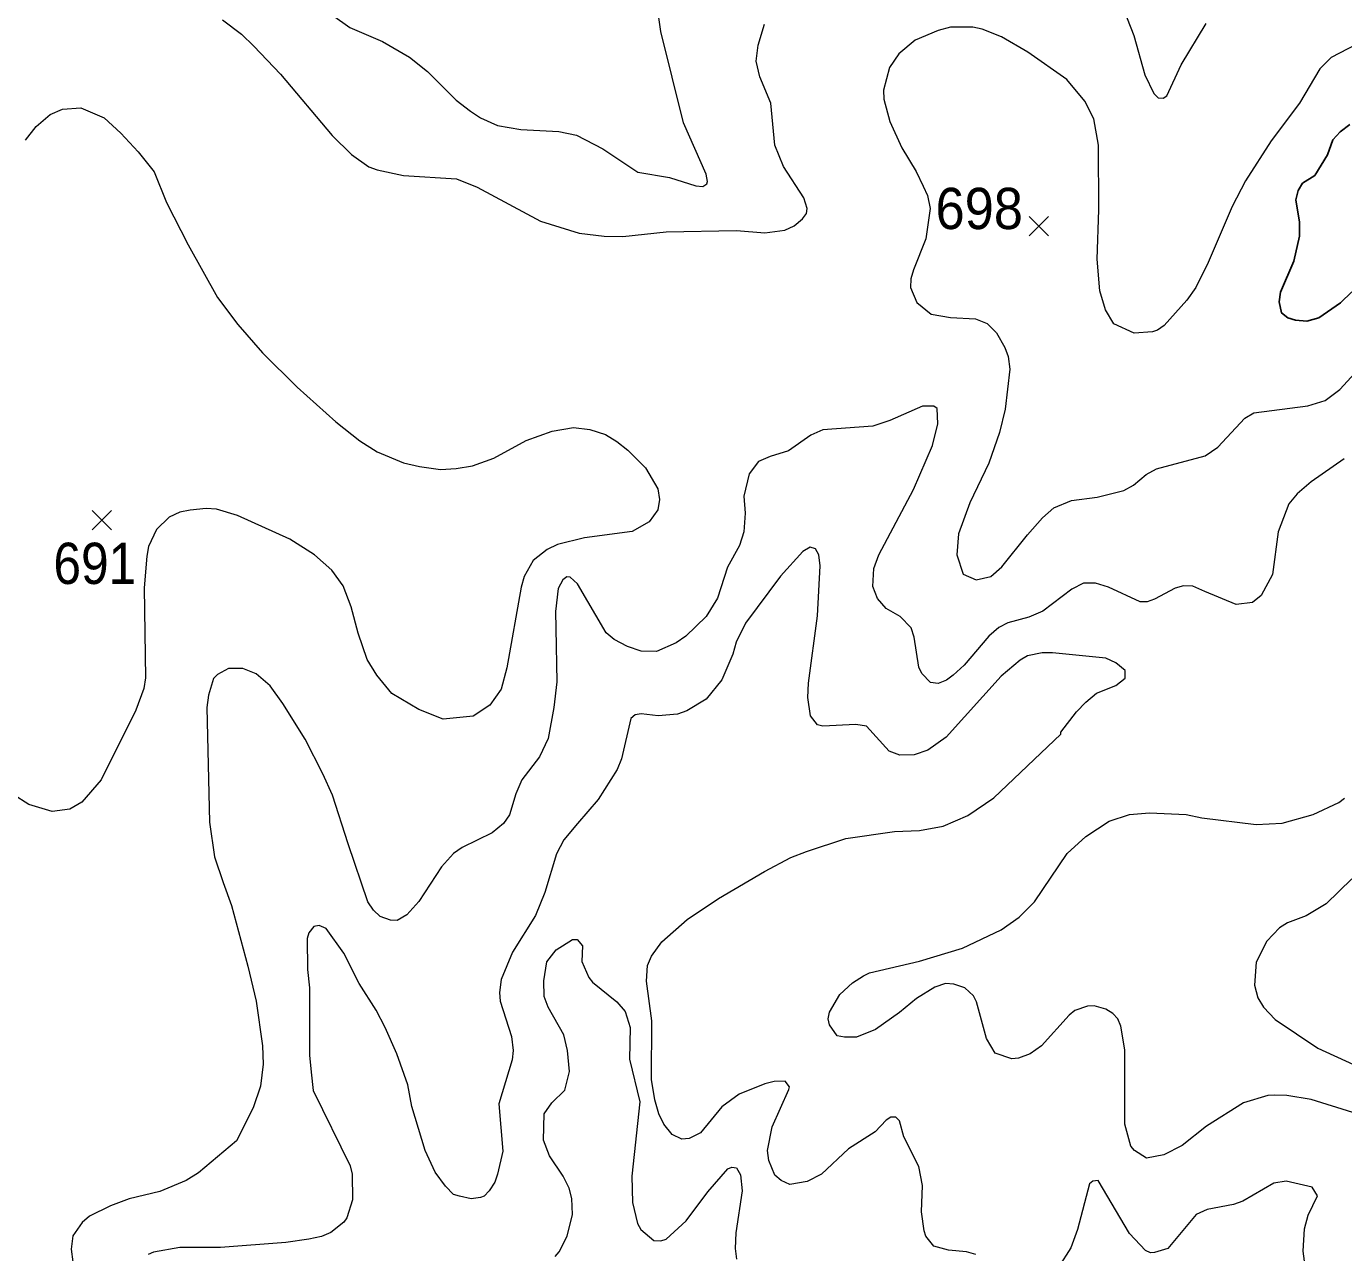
# Model space of a CAD drawing. Extents: x 294.2 to 320.3, y 7482.7 to 7510.7.
# Drawn here: x 301.736 to 304.291, y 7497.059 to 7499.438 of the extents above; entities that cross this region are included whole.
import ezdxf
from ezdxf.enums import TextEntityAlignment as Align

# ---------------------------------------------------------------- set-up
doc = ezdxf.new("R2010")
doc.units = 0
doc.header["$LTSCALE"] = 0.032
for name, color, linetype, lineweight in [('1', 7, 'Continuous', 25), ('2', 7, 'Continuous', 13), ('21', 7, 'Continuous', 25)]:
    doc.layers.add(name, color=color, linetype=linetype, lineweight=lineweight)
doc.layers.add('61', color=7, linetype='Continuous')

msp = doc.modelspace()

# ---------------------------------------------------------------- linework, layer by layer
at = {"layer": '1'}
msp.add_lwpolyline([(304.3071, 7498.9229), (304.2851, 7498.9017), (304.2434, 7498.8726), (304.2198, 7498.8663), (304.1978, 7498.8679), (304.1829, 7498.8726), (304.1711, 7498.8821), (304.1664, 7498.9033), (304.1687, 7498.9222), (304.195, 7498.9827), (304.206, 7499.0307), (304.206, 7499.0582), (304.1986, 7499.1014), (304.2033, 7499.1195), (304.2119, 7499.1337), (304.2355, 7499.1486), (304.2599, 7499.1887), (304.2705, 7499.2178), (304.2847, 7499.2335), (304.3035, 7499.2477)], dxfattribs=at)
at = {"layer": '2'}
for points in [[(302.3298, 7499.4594), (302.3636, 7499.4357), (302.4268, 7499.4083), (302.4792, 7499.3782), (302.5143, 7499.3502), (302.5366, 7499.3278), (302.5698, 7499.2946), (302.5979, 7499.2735), (302.6171, 7499.2608), (302.6503, 7499.2454), (302.695, 7499.2378), (302.7691, 7499.234), (302.8035, 7499.227), (302.8546, 7499.2002), (302.9223, 7499.1548), (302.9836, 7499.1446), (303.0347, 7499.1286), (303.0481, 7499.1274), (303.0563, 7499.1324), (303.0576, 7499.137), (303.0545, 7499.151), (303.011, 7499.2506), (302.9669, 7499.4281), (302.9631, 7499.4549)], [(303.8646, 7499.4715), (303.8845, 7499.4204), (303.9055, 7499.3438), (303.9234, 7499.308), (303.9317, 7499.2991), (303.9413, 7499.2985), (303.9483, 7499.3029), (303.9764, 7499.363), (304.0249, 7499.4434)], [(302.1165, 7499.4504), (302.1536, 7499.423), (302.1772, 7499.3993), (302.2289, 7499.3451), (302.3291, 7499.2263), (302.3668, 7499.1893), (302.4006, 7499.1657), (302.4166, 7499.1593), (302.4677, 7499.1484), (302.5705, 7499.142), (302.6107, 7499.1261), (302.7333, 7499.0603), (302.8087, 7499.0367), (302.8572, 7499.0309), (302.8929, 7499.0303), (302.9772, 7499.0393), (303.1138, 7499.0418), (303.1687, 7499.0373), (303.2071, 7499.0424), (303.2256, 7499.0507), (303.2415, 7499.0648), (303.2492, 7499.075), (303.2504, 7499.0846), (303.244, 7499.105), (303.2051, 7499.1663), (303.1879, 7499.2072), (303.1802, 7499.2889), (303.1592, 7499.34), (303.1521, 7499.3706), (303.1559, 7499.4013), (303.1681, 7499.4421)], [(303.5289, 7499.4364), (303.5046, 7499.43), (303.4599, 7499.4109), (303.4286, 7499.3846), (303.4107, 7499.3579), (303.3986, 7499.3144), (303.3992, 7499.2966), (303.4113, 7499.2532), (303.4343, 7499.2021), (303.4624, 7499.1567), (303.4759, 7499.128), (303.4841, 7499.1101), (303.4892, 7499.0846), (303.481, 7499.0259), (303.4567, 7498.9658), (303.4516, 7498.948), (303.4509, 7498.9314), (303.4637, 7498.902), (303.4911, 7498.8796), (303.5289, 7498.8733), (303.5774, 7498.8707), (303.5997, 7498.8617), (303.6182, 7498.8432), (303.6342, 7498.8152), (303.6406, 7498.7973), (303.6437, 7498.773), (303.6348, 7498.6951), (303.624, 7498.6504), (303.6029, 7498.5904), (303.5665, 7498.5138), (303.5441, 7498.4538), (303.541, 7498.4129), (303.5531, 7498.3752), (303.5787, 7498.3643), (303.6067, 7498.3708), (303.6285, 7498.3893), (303.6782, 7498.4518), (303.707, 7498.4844), (303.7293, 7498.5042), (303.7638, 7498.5183), (303.8136, 7498.5246), (303.8647, 7498.5374), (303.8838, 7498.5482), (303.9081, 7498.5687), (303.9285, 7498.5796), (304.023, 7498.6051), (304.0473, 7498.6217), (304.0996, 7498.6779), (304.1175, 7498.6881), (304.2222, 7498.7021), (304.2554, 7498.7124), (304.2841, 7498.7334), (304.3282, 7498.7813)], [(303.7893, 7499.2927), (303.7542, 7499.3349), (303.6789, 7499.3879), (303.6278, 7499.4178), (303.5901, 7499.4326), (303.5723, 7499.4364), (303.5289, 7499.4364)], [(304.3467, 7499.4191), (304.2675, 7499.3776), (304.2452, 7499.3553), (304.2056, 7499.2889), (304.1507, 7499.2161), (304.1009, 7499.1382), (304.0754, 7499.0884), (304.0288, 7498.9799), (304.0045, 7498.9314), (303.9872, 7498.9071), (303.9432, 7498.8579), (303.9304, 7498.8483), (303.9209, 7498.8452), (303.8851, 7498.8426), (303.8455, 7498.8611), (303.8296, 7498.8879), (303.8187, 7498.925), (303.8136, 7498.9863), (303.8168, 7499.082), (303.8161, 7499.2072), (303.8066, 7499.2583), (303.7893, 7499.2927)], [(301.7347, 7499.2174), (301.7551, 7499.2436), (301.782, 7499.2672), (301.8062, 7499.2774), (301.842, 7499.2799), (301.8867, 7499.2602), (301.9192, 7499.2308), (301.9531, 7499.1944), (301.9837, 7499.1555), (302.008, 7499.0961), (302.0501, 7499.0144), (302.1069, 7498.9122), (302.1465, 7498.8598), (302.1944, 7498.8049), (302.2615, 7498.7379), (302.3362, 7498.6708), (302.3827, 7498.6338), (302.4166, 7498.6128), (302.4677, 7498.591), (302.4984, 7498.584), (302.5392, 7498.5783), (302.5699, 7498.5802), (302.6018, 7498.5853), (302.6426, 7498.6), (302.7058, 7498.6345), (302.7563, 7498.6529), (302.7972, 7498.66), (302.8291, 7498.6562), (302.8597, 7498.646), (302.8814, 7498.6325), (302.9031, 7498.6159), (302.937, 7498.5815), (302.9612, 7498.5406), (302.9644, 7498.5202), (302.9612, 7498.4998), (302.944, 7498.4767), (302.9114, 7498.4582), (302.8189, 7498.4455), (302.7665, 7498.4327), (302.7461, 7498.4231), (302.7192, 7498.4021), (302.702, 7498.3708), (302.6962, 7498.3503), (302.6681, 7498.1933), (302.6573, 7498.1524), (302.6349, 7498.1211), (302.6031, 7498.1), (302.5449, 7498.0943), (302.4971, 7498.1128), (302.4453, 7498.1441), (302.416, 7498.1792), (302.3974, 7498.2099), (302.3795, 7498.261), (302.3662, 7498.312), (302.3509, 7498.3529), (302.3285, 7498.3829), (302.2947, 7498.4129), (302.2474, 7498.4429), (302.1459, 7498.4889), (302.1051, 7498.5017), (302.0846, 7498.5029), (302.054, 7498.4997), (302.0335, 7498.4953), (302.0131, 7498.4857), (301.9882, 7498.4621), (301.9729, 7498.4289), (301.9696, 7498.4104), (301.9645, 7498.3491)], [(303.6029, 7498.2552), (303.555, 7498.199), (303.534, 7498.1792), (303.5212, 7498.1697), (303.5046, 7498.1633), (303.4899, 7498.1651), (303.4733, 7498.1824), (303.4675, 7498.1946), (303.4586, 7498.2533), (303.4522, 7498.2712), (303.4312, 7498.2935), (303.4037, 7498.3088), (303.3871, 7498.328), (303.3781, 7498.3516), (303.3801, 7498.3861), (303.3896, 7498.4129), (303.4567, 7498.5393), (303.4937, 7498.6249), (303.5045, 7498.667), (303.5027, 7498.6964), (303.4963, 7498.7015), (303.4745, 7498.7015), (303.4114, 7498.6734), (303.3782, 7498.6626), (303.2811, 7498.6555), (303.2581, 7498.6447), (303.2147, 7498.6146), (303.179, 7498.6038), (303.156, 7498.5936), (303.1381, 7498.57), (303.1278, 7498.5266), (303.1304, 7498.4934), (303.1278, 7498.4576), (303.1196, 7498.4308), (303.0959, 7498.3887), (303.0768, 7498.3286), (303.0551, 7498.2935), (303.0155, 7498.2552), (302.9964, 7498.2418), (302.9587, 7498.2252), (302.9287, 7498.2258), (302.9019, 7498.2348), (302.8763, 7498.2488), (302.861, 7498.2616), (302.8055, 7498.3567), (302.7908, 7498.3695), (302.7844, 7498.3701), (302.7767, 7498.3643), (302.7677, 7498.3478), (302.7626, 7498.3031), (302.7633, 7498.2699), (302.7652, 7498.1665), (302.7595, 7498.1167), (302.748, 7498.0566), (302.7314, 7498.0209), (302.6975, 7497.9762), (302.6854, 7497.9494), (302.6732, 7497.9085), (302.6618, 7497.8919), (302.6394, 7497.8734), (302.5814, 7497.8453), (302.5648, 7497.8332), (302.5411, 7497.8076), (302.4977, 7497.7406), (302.4741, 7497.7144), (302.4556, 7497.7036), (302.4422, 7497.7042), (302.4223, 7497.7112), (302.4096, 7497.7233), (302.3987, 7497.74), (302.3604, 7497.8523), (302.3297, 7497.9468), (302.3113, 7497.9877), (302.2768, 7498.0554), (302.2334, 7498.1243), (302.2091, 7498.1588), (302.1816, 7498.1817), (302.1561, 7498.1926), (302.128, 7498.1926), (302.1069, 7498.1805), (302.0993, 7498.1728), (302.0891, 7498.1409), (302.0859, 7498.1167), (302.0916, 7497.8945), (302.1012, 7497.8268), (302.1178, 7497.777), (302.1338, 7497.7323), (302.1657, 7497.6148), (302.1816, 7497.5471), (302.1944, 7497.4603), (302.1951, 7497.4246), (302.19, 7497.3824), (302.1759, 7497.3403), (302.1434, 7497.2758), (302.0699, 7497.2138)], [(304.2924, 7498.5993), (304.2286, 7498.5546), (304.2011, 7498.531), (304.1852, 7498.5119), (304.1647, 7498.4576), (304.1532, 7498.3746), (304.1315, 7498.3337), (304.1143, 7498.3203), (304.083, 7498.3165), (304.0224, 7498.342), (303.9988, 7498.3523), (303.9809, 7498.3529), (303.9643, 7498.3484), (303.9247, 7498.3267), (303.91, 7498.3216), (303.8966, 7498.3216), (303.8353, 7498.3503), (303.8098, 7498.358), (303.7868, 7498.358)], [(303.7268, 7498.2226), (303.7064, 7498.2226), (303.6783, 7498.2169), (303.6636, 7498.2086), (303.6272, 7498.1773), (303.5205, 7498.0592), (303.4848, 7498.0336), (303.4586, 7498.0247), (303.4305, 7498.0241), (303.4101, 7498.0317), (303.366, 7498.0803), (303.345, 7498.0834), (303.2811, 7498.0803), (303.2709, 7498.0828), (303.2575, 7498.1007), (303.2517, 7498.1358), (303.253, 7498.1639), (303.2709, 7498.2942), (303.276, 7498.3912), (303.2734, 7498.4129), (303.267, 7498.4244), (303.2568, 7498.4276), (303.2421, 7498.4193), (303.1987, 7498.3714), (303.1311, 7498.2801), (303.1132, 7498.2437), (303.1068, 7498.2201), (303.0851, 7498.1703), (303.0545, 7498.1326), (303.0174, 7498.1102), (302.9989, 7498.1038), (302.9619, 7498.1007), (302.9287, 7498.1045), (302.9172, 7498.1026), (302.9089, 7498.0956), (302.8903, 7498.0171), (302.8821, 7497.9966), (302.8456, 7497.9379), (302.8054, 7497.8919), (302.7786, 7497.86), (302.7646, 7497.8325), (302.7416, 7497.7578), (302.7237, 7497.7131), (302.679, 7497.6423), (302.6573, 7497.5893), (302.6541, 7497.5637), (302.6554, 7497.5471), (302.6771, 7497.4782), (302.6803, 7497.4514), (302.6784, 7497.4335), (302.6528, 7497.3479), (302.6605, 7497.256), (302.6503, 7497.2113), (302.6446, 7497.196), (302.6337, 7497.1794), (302.6241, 7497.1685), (302.6171, 7497.166), (302.5992, 7497.1634), (302.5762, 7497.1685), (302.5647, 7497.1723), (302.5494, 7497.1883), (302.529, 7497.2151), (302.5098, 7497.2573), (302.4837, 7497.3428), (302.476, 7497.385), (302.4549, 7497.445), (302.4319, 7497.4961), (302.4147, 7497.5293), (302.3815, 7497.5816), (302.3521, 7497.6404), (302.3177, 7497.6882), (302.3043, 7497.6939), (302.2934, 7497.6921), (302.2838, 7497.6793), (302.2806, 7497.6685), (302.2812, 7497.6084), (302.2851, 7497.5727), (302.2851, 7497.4424), (302.2883, 7497.4092), (302.2927, 7497.3735), (302.3642, 7497.2279), (302.3681, 7497.2113), (302.3687, 7497.1615), (302.3579, 7497.127), (302.3521, 7497.1181), (302.3266, 7497.0983), (302.3087, 7497.0906), (302.2838, 7497.0855), (302.2391, 7497.0791), (302.1127, 7497.0695), (302.0335, 7497.0689), (301.9825, 7497.06), (301.9722, 7497.0555)], [(303.7868, 7498.358), (303.7644, 7498.3459), (303.7076, 7498.3037), (303.6808, 7498.2922), (303.6399, 7498.2807), (303.6227, 7498.2718), (303.6029, 7498.2552)], [(301.9645, 7498.3491), (301.9671, 7498.1741), (301.9639, 7498.1537), (301.9486, 7498.1116), (301.8809, 7497.9762), (301.8439, 7497.9328), (301.8203, 7497.9194), (301.7858, 7497.9149)], [(303.8123, 7498.1447), (303.8494, 7498.1594), (303.8679, 7498.1735), (303.8679, 7498.1882), (303.8493, 7498.2035), (303.8302, 7498.2124), (303.7268, 7498.2226)], [(303.578, 7497.0555), (303.5595, 7497.0606), (303.525, 7497.0638), (303.4963, 7497.0721), (303.481, 7497.0913), (303.4777, 7497.1015), (303.4726, 7497.1385), (303.4746, 7497.1896), (303.4675, 7497.2266), (303.4381, 7497.2841), (303.4299, 7497.3147), (303.4228, 7497.3217), (303.4127, 7497.3218), (303.4037, 7497.316), (303.3826, 7497.2937), (303.3309, 7497.2605), (303.2786, 7497.2113), (303.2505, 7497.1972), (303.2173, 7497.1915), (303.2, 7497.1992), (303.1879, 7497.2094), (303.1764, 7497.2381), (303.1738, 7497.2573), (303.1828, 7497.3032), (303.2153, 7497.3754), (303.2166, 7497.3811), (303.2083, 7497.392), (303.1866, 7497.3913), (303.1688, 7497.3869), (303.119, 7497.3664), (303.0851, 7497.3422), (303.0436, 7497.2917), (303.0219, 7497.2809), (303.0078, 7497.2796), (302.9887, 7497.2885), (302.9727, 7497.3084), (302.9631, 7497.3288), (302.9555, 7497.3556), (302.9485, 7497.3952), (302.9491, 7497.5088), (302.9389, 7497.5855), (302.9408, 7497.6161), (302.9485, 7497.634), (302.9689, 7497.6621), (303.018, 7497.7055), (303.0787, 7497.7463), (303.1681, 7497.7987), (303.2192, 7497.8255), (303.2492, 7497.8376), (303.3258, 7497.8625), (303.4203, 7497.8759), (303.4688, 7497.8778), (303.5148, 7497.8868), (303.5621, 7497.9072), (303.6131, 7497.9417), (303.7427, 7498.0649), (303.7427, 7498.0688), (303.7734, 7498.1083), (303.7913, 7498.1269), (303.8123, 7498.1447)], [(301.7858, 7497.9149), (301.7411, 7497.9283), (301.7105, 7497.9481)], [(303.5352, 7497.5797), (303.5193, 7497.581), (303.4982, 7497.5739), (303.4625, 7497.5522), (303.4299, 7497.5248), (303.3833, 7497.4922), (303.3462, 7497.4775), (303.3233, 7497.4769), (303.3092, 7497.4801), (303.2938, 7497.5012), (303.2913, 7497.5127), (303.2938, 7497.5254), (303.3143, 7497.5599), (303.3386, 7497.5829), (303.3603, 7497.5963), (303.3718, 7497.602), (303.4688, 7497.6244), (303.5518, 7497.6499), (303.6272, 7497.6857), (303.6617, 7497.7099), (303.6916, 7497.7399), (303.7548, 7497.8332), (303.7913, 7497.8664), (303.8366, 7497.8964), (303.8762, 7497.9092), (303.9145, 7497.9123), (303.986, 7497.9092), (304.0166, 7497.9028), (304.1214, 7497.89), (304.1724, 7497.8926), (304.2325, 7497.9092), (304.2823, 7497.9321), (304.2931, 7497.9411)], [(304.3071, 7497.784), (304.2573, 7497.7361), (304.2184, 7497.7125), (304.1827, 7497.6991), (304.1673, 7497.6895), (304.1424, 7497.6633), (304.122, 7497.6225), (304.1182, 7497.5778), (304.1251, 7497.5535), (304.136, 7497.5357), (304.1584, 7497.5113), (304.2414, 7497.4558), (304.3103, 7497.4239)], [(302.762, 7497.0517), (302.7697, 7497.0606), (302.785, 7497.0913), (302.7952, 7497.1334), (302.794, 7497.1641), (302.7889, 7497.1845), (302.7774, 7497.2075), (302.7511, 7497.2471), (302.7391, 7497.2777), (302.7403, 7497.3288), (302.7556, 7497.3498), (302.7806, 7497.3747), (302.7895, 7497.4105), (302.7856, 7497.4514), (302.7786, 7497.482), (302.748, 7497.5357), (302.7403, 7497.5561), (302.7397, 7497.5867), (302.746, 7497.6231), (302.764, 7497.6467), (302.7952, 7497.6665), (302.8048, 7497.6665), (302.815, 7497.6544), (302.8137, 7497.6238), (302.8272, 7497.5931), (302.8342, 7497.5841), (302.8814, 7497.5458), (302.8974, 7497.5267), (302.9076, 7497.4961), (302.9063, 7497.4348), (302.9261, 7497.3518), (302.9108, 7497.2075), (302.912, 7497.1564)], [(303.6476, 7497.4354), (303.6157, 7497.4462), (303.5984, 7497.4744), (303.5793, 7497.5459), (303.5735, 7497.5574), (303.5563, 7497.5727), (303.5352, 7497.5797)], [(304.3799, 7497.309), (304.2286, 7497.3562), (304.1814, 7497.3639), (304.1571, 7497.3645), (304.1443, 7497.3639), (304.0971, 7497.3498), (304.0256, 7497.3045), (303.9783, 7497.2668), (303.9426, 7497.249), (303.9087, 7497.2426), (303.8858, 7497.2573), (303.8787, 7497.2655), (303.8672, 7497.3084), (303.8672, 7497.4526), (303.8595, 7497.4986), (303.8532, 7497.5126), (303.8436, 7497.5229), (303.8302, 7497.5312), (303.8072, 7497.5382), (303.7945, 7497.5376), (303.7702, 7497.5286), (303.7587, 7497.5197), (303.7051, 7497.4603), (303.6834, 7497.445), (303.6604, 7497.4367), (303.6476, 7497.4354)], [(302.0699, 7497.2138), (302.0463, 7497.1992), (301.9952, 7497.1775), (301.9352, 7497.1634), (301.8995, 7497.15), (301.8586, 7497.1302), (301.8446, 7497.1174)], [(303.0161, 7497.1212), (303.0583, 7497.1774), (303.0966, 7497.2215), (303.1049, 7497.2253), (303.1138, 7497.224), (303.1215, 7497.21), (303.1247, 7497.1794), (303.1125, 7497.0977), (303.1112, 7497.067), (303.1138, 7497.0466)], [(304.2184, 7497.0185), (304.2126, 7497.0619), (304.2158, 7497.1053), (304.2229, 7497.1321), (304.2407, 7497.1691), (304.2305, 7497.1864), (304.1801, 7497.1979), (304.1558, 7497.1941), (304.0958, 7497.1589), (304.0779, 7497.1525), (304.0269, 7497.143), (304.0051, 7497.1334), (303.9502, 7497.067), (303.9247, 7497.0593), (303.917, 7497.0587), (303.9068, 7497.0631), (303.8762, 7497.0964), (303.8149, 7497.1992), (303.8047, 7497.1979), (303.7983, 7497.1928), (303.7753, 7497.104), (303.7625, 7497.0683), (303.7382, 7497.0312)], [(302.912, 7497.1564), (302.9216, 7497.1155), (302.928, 7497.104), (302.9535, 7497.083), (302.967, 7497.0823), (302.9772, 7497.0855), (303.0161, 7497.1212)], [(301.8446, 7497.1174), (301.826, 7497.0919), (301.8228, 7497.0657), (301.826, 7497.0415)]]:
    msp.add_lwpolyline(points, dxfattribs=at)
at = {"layer": '21'}
for p, q in [((303.6815, 7499.0691), (303.719, 7499.0316)), ((303.719, 7499.0691), (303.6815, 7499.0316)), ((301.8634, 7498.4987), (301.9009, 7498.4612)), ((301.9009, 7498.4987), (301.8634, 7498.4612))]:
    msp.add_line(p, q, dxfattribs=at)

# ---------------------------------------------------------------- texts
at = {"layer": '61'}
for s, width, p in [('698', 0.95, (303.5845, 7499.0447)), ('691', 0.9, (301.8689, 7498.3563))]:
    msp.add_text(s, height=0.08, dxfattribs=dict(at, width=width)).set_placement(p, align=Align.CENTER)

doc.saveas('drawing.dxf')
